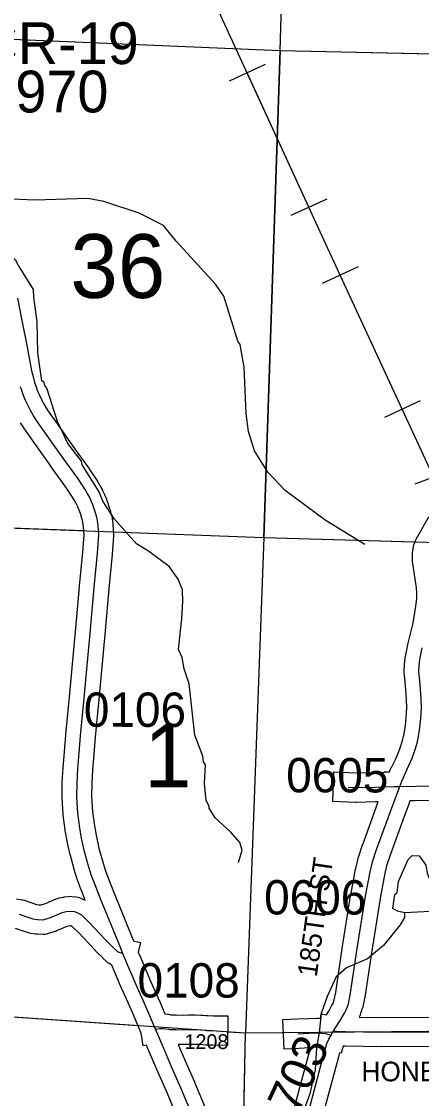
# Model space of a CAD drawing. Extents: x -132.8 to -73.3, y -60 to -26.
# Drawn here: x -122.216 to -121.401, y -45.505 to -43.311 of the extents above; entities that cross this region are included whole.
import ezdxf

# ---------------------------------------------------------------- set-up
doc = ezdxf.new("R2010")
doc.units = 0
for name, color, linetype in [('tdCoHydroRiver', 7, 'Continuous'), ('tdCoPipe', 7, 'Continuous'), ('tdCoSecRdNmbr', 7, 'Continuous'), ('tdCoSecRdTxt', 7, 'Continuous'), ('tdCoSecRteBand', 7, 'Continuous'), ('tdCoSecRteCL', 7, 'Continuous'), ('tdCoSectLine', 7, 'Continuous'), ('tdCoSectLinePart', 7, 'Continuous'), ('tdCoSectNmbr', 7, 'Continuous'), ('tdCoStrucSecCoName', 7, 'Continuous'), ('tdCoStrucSecFHWANum', 7, 'Continuous'), ('tdCoSurfAsphalt', 7, 'Continuous'), ('tdCoSurfBitum', 7, 'Continuous'), ('tdCoSurfGravel', 7, 'Continuous'), ('tdCoTwpBndry', 7, 'Continuous'), ('tdCoTwpBndryShd', 7, 'Continuous')]:
    doc.layers.add(name, color=color, linetype=linetype)

msp = doc.modelspace()

# ---------------------------------------------------------------- linework, layer by layer
at = {"layer": 'tdCoHydroRiver'}
for points in [[(-121.5159, -44.3765), (-121.5967, -44.3269), (-121.6787, -44.2663), (-121.714, -44.2291), (-121.7412, -44.1858), (-121.7528, -44.146), (-121.7581, -44.1096), (-121.7619, -44.0148), (-121.7701, -43.9689), (-121.7747, -43.9624), (-121.8037, -43.8701), (-121.8204, -43.846), (-121.9002, -43.7587), (-121.9261, -43.7264), (-121.9759, -43.7014), (-122.0479, -43.6774), (-122.0809, -43.6717), (-122.1883, -43.6751), (-122.2498, -43.6719)], [(-122.1839, -43.9229), (-122.1905, -43.8723), (-122.1916, -43.8565), (-122.2203, -43.81), (-122.2219, -43.8083), (-122.2264, -43.7987), (-122.2341, -43.7922), (-122.2501, -43.7413)], [(-122.1825, -43.9861), (-122.1839, -43.9229)], [(-121.7733, -45.0242), (-121.7663, -44.9991), (-121.7706, -44.9833), (-121.789, -44.9622), (-121.8213, -44.933), (-121.8334, -44.9137), (-121.8333, -44.909), (-121.8393, -44.8978), (-121.8431, -44.863), (-121.8405, -44.8252), (-121.8451, -44.8187), (-121.8463, -44.8077), (-121.8626, -44.7646), (-121.8739, -44.6602), (-121.8842, -44.6299), (-121.8883, -44.6062), (-121.8957, -44.5902), (-121.8893, -44.5273), (-121.8868, -44.4926), (-121.8877, -44.4689), (-121.8966, -44.4466), (-121.9148, -44.4209), (-121.9566, -44.3898), (-121.9815, -44.3749), (-122.0259, -44.3248), (-122.0501, -44.2878), (-122.0575, -44.2687), (-122.0924, -44.2141), (-122.0937, -44.2062), (-122.1212, -44.1708), (-122.1421, -44.126), (-122.1639, -44.0576), (-122.1685, -44.0527), (-122.1699, -44.0464), (-122.1745, -44.0431), (-122.1825, -43.9861)], [(-121.4351, -45.1264), (-121.4492, -45.1229), (-121.4586, -45.1179), (-121.4546, -45.0896), (-121.4498, -45.085), (-121.4476, -45.063), (-121.4275, -45.0178), (-121.4194, -45.0101), (-121.4052, -45.0105), (-121.3915, -45.0298), (-121.3887, -45.0457), (-121.3784, -45.0727), (-121.3758, -45.0918), (-121.3712, -45.0966), (-121.3687, -45.1235), (-121.4351, -45.1264)], [(-121.4351, -45.1264), (-121.4354, -45.1359), (-121.4437, -45.1514), (-121.4779, -45.1931), (-121.5103, -45.2206), (-121.5533, -45.2384), (-121.5744, -45.2568), (-121.5928, -45.2973), (-121.6048, -45.3317), (-121.609, -45.371), (-121.6145, -45.4008), (-121.6173, -45.4465), (-121.6281, -45.4951), (-121.6605, -45.5842)]]:
    msp.add_lwpolyline(points, dxfattribs=at)
at = {"layer": 'tdCoPipe'}
for p, q in [((-121.7192, -43.3986), (-121.7925, -43.4323)), ((-121.5935, -43.6725), (-121.6667, -43.7061)), ((-121.5298, -43.8105), (-121.603, -43.8444)), ((-121.4031, -44.0839), (-121.4762, -44.1178)), ((-121.3386, -44.2253), (-121.4143, -44.2532))]:
    msp.add_line(p, q, dxfattribs=at)
for points in [[(-119.9584, -47.7616), (-119.9471, -47.3844), (-120.3344, -46.3596), (-120.5772, -46.3668), (-120.6441, -46.2979), (-120.7015, -46.0564), (-120.837, -45.9047), (-120.8751, -45.6974), (-120.9717, -45.5088), (-121.2124, -44.6836), (-121.3801, -44.2294), (-121.5957, -43.7643), (-121.8285, -43.2571), (-122.1175, -42.7469), (-122.5487, -41.6141), (-122.6831, -41.5141), (-123.1262, -40.7823)], [(-121.6301, -43.6893), (-121.7558, -43.4155)], [(-121.4397, -44.1008), (-121.5664, -43.8275)]]:
    msp.add_lwpolyline(points, dxfattribs=at)
at = {"layer": 'tdCoSecRteBand'}
for points in [[(-122.2236, -43.8744), (-122.215, -43.9199), (-122.2044, -43.9738), (-122.2044, -43.9739), (-122.2044, -43.974), (-122.1951, -44.0228), (-122.1936, -44.0296), (-122.1916, -44.0367), (-122.189, -44.0462), (-122.1861, -44.055), (-122.1829, -44.0637), (-122.1793, -44.0723), (-122.1753, -44.0807), (-122.171, -44.0889), (-122.1664, -44.097), (-122.1615, -44.1047), (-122.1427, -44.1315), (-122.1063, -44.1829), (-122.0775, -44.223), (-122.0772, -44.2234), (-122.0769, -44.2238), (-122.0612, -44.2475), (-122.0607, -44.2482), (-122.0603, -44.2488), (-122.0558, -44.2564), (-122.0555, -44.257), (-122.0552, -44.2576), (-122.051, -44.2653), (-122.0507, -44.2659), (-122.0504, -44.2665), (-122.0467, -44.2745), (-122.0464, -44.2751), (-122.0461, -44.2757), (-122.0427, -44.2838), (-122.0424, -44.2844), (-122.0422, -44.2851), (-122.0392, -44.2933), (-122.039, -44.294), (-122.0388, -44.2946), (-122.0361, -44.303), (-122.0359, -44.3037), (-122.0357, -44.3043), (-122.0335, -44.3128), (-122.0333, -44.3135), (-122.0332, -44.3141), (-122.0313, -44.3227), (-122.0312, -44.3234), (-122.0311, -44.3241), (-122.0296, -44.3327), (-122.0294, -44.3344), (-122.0293, -44.3361), (-122.0283, -44.3553), (-122.0282, -44.3572), (-122.0283, -44.3591), (-122.031, -44.3963), (-122.0311, -44.3966), (-122.0311, -44.397), (-122.0377, -44.4669), (-122.0451, -44.5521), (-122.0451, -44.5522), (-122.0451, -44.5523), (-122.0493, -44.5966), (-122.058, -44.6918), (-122.058, -44.6918), (-122.058, -44.6919), (-122.0654, -44.769), (-122.0683, -44.8036), (-122.0683, -44.8037), (-122.0683, -44.8038), (-122.0712, -44.8352), (-122.0726, -44.8632), (-122.0731, -44.8896), (-122.071, -44.9209), (-122.0673, -44.9491), (-122.0638, -44.9687), (-122.058, -44.9948), (-122.0516, -45.0185), (-122.0444, -45.0414), (-122.0379, -45.0591), (-122.027, -45.0867), (-121.9906, -45.1758), (-121.9873, -45.1836), (-121.9731, -45.1869), (-121.9778, -45.2067), (-121.9734, -45.2172), (-121.9546, -45.261), (-121.9349, -45.3052), (-121.9348, -45.3054), (-121.9347, -45.3056), (-121.9269, -45.3239), (-121.9233, -45.3324), (-121.9177, -45.3331), (-121.9169, -45.3332), (-121.9161, -45.3333), (-121.9113, -45.3342), (-121.91, -45.3343), (-121.9068, -45.3345), (-121.9006, -45.3346), (-121.8875, -45.3348), (-121.8751, -45.3346), (-121.8749, -45.3346), (-121.8747, -45.3346), (-121.8636, -45.3346), (-121.8634, -45.3346), (-121.8633, -45.3346), (-121.85, -45.3348), (-121.8485, -45.3348), (-121.847, -45.335), (-121.8391, -45.3358), (-121.8362, -45.3361), (-121.8253, -45.3362), (-121.7953, -45.3366), (-121.796, -45.3966), (-121.826, -45.3962), (-121.8382, -45.3961), (-121.8395, -45.3961), (-121.8408, -45.396), (-121.8452, -45.3955), (-121.8453, -45.3955), (-121.8455, -45.3955), (-121.8521, -45.3948), (-121.8638, -45.3946), (-121.8746, -45.3946), (-121.8871, -45.3948), (-121.8875, -45.3948), (-121.8878, -45.3948), (-121.8966, -45.3947), (-121.8823, -45.428), (-121.8634, -45.4707), (-121.8632, -45.4711), (-121.8631, -45.4714), (-121.8402, -45.5265)], [(-122.2262, -45.098), (-122.2151, -45.1), (-122.2128, -45.1004), (-122.2106, -45.1011), (-122.195, -45.1065), (-122.1855, -45.1096), (-122.1803, -45.1104), (-122.1754, -45.1105), (-122.1668, -45.1079), (-122.1448, -45.0983), (-122.142, -45.0971), (-122.139, -45.0964), (-122.1309, -45.0947), (-122.1296, -45.0944), (-122.1283, -45.0943), (-122.1201, -45.0933), (-122.1167, -45.0929), (-122.1132, -45.0933), (-122.1043, -45.0942), (-122.1003, -45.0947), (-122.0965, -45.0962), (-122.0891, -45.0992), (-122.0874, -45.0999), (-122.086, -45.1006), (-122.0938, -45.0808), (-122.0939, -45.0805), (-122.094, -45.0802), (-122.1009, -45.0614), (-122.1012, -45.0608), (-122.1014, -45.0601), (-122.109, -45.036), (-122.1092, -45.0353), (-122.1094, -45.0347), (-122.1161, -45.0098), (-122.1162, -45.0092), (-122.1164, -45.0086), (-122.1225, -44.9812), (-122.1227, -44.9805), (-122.1228, -44.9798), (-122.1265, -44.9589), (-122.1266, -44.9582), (-122.1267, -44.9576), (-122.1307, -44.9278), (-122.1308, -44.9268), (-122.1308, -44.9258), (-122.1331, -44.8923), (-122.1331, -44.891), (-122.1331, -44.8898), (-122.1326, -44.8617), (-122.1326, -44.8612), (-122.1326, -44.8607), (-122.1311, -44.8316), (-122.1311, -44.8309), (-122.131, -44.8303), (-122.1281, -44.7984), (-122.1251, -44.7637), (-122.1251, -44.7635), (-122.1251, -44.7634), (-122.1177, -44.6863), (-122.1091, -44.5912), (-122.1091, -44.5911), (-122.1091, -44.591), (-122.1049, -44.5468), (-122.0975, -44.4616), (-122.0975, -44.4614), (-122.0975, -44.4613), (-122.0909, -44.3916), (-122.0883, -44.3566), (-122.0891, -44.3409), (-122.0902, -44.3346), (-122.0917, -44.3274), (-122.0936, -44.3203), (-122.0958, -44.3133), (-122.0983, -44.3064), (-122.1012, -44.2996), (-122.1043, -44.2929), (-122.1078, -44.2864), (-122.1115, -44.2801), (-122.1266, -44.2576), (-122.1551, -44.2178), (-122.1552, -44.2177), (-122.1552, -44.2176), (-122.1917, -44.1661), (-122.1918, -44.166), (-122.1918, -44.166), (-122.211, -44.1386), (-122.2115, -44.138), (-122.2118, -44.1374), (-122.2175, -44.1285)], [(-121.6619, -45.533), (-121.6311, -45.417), (-121.6311, -45.4168), (-121.631, -45.4166), (-121.6268, -45.4018), (-121.6287, -45.4018), (-121.6507, -45.4028), (-121.6807, -45.4041), (-121.6833, -45.3442), (-121.6533, -45.3428), (-121.6312, -45.3419), (-121.6309, -45.3418), (-121.6306, -45.3418), (-121.6124, -45.3413), (-121.611, -45.3413), (-121.6095, -45.3414), (-121.6066, -45.3416), (-121.6053, -45.3327), (-121.5943, -45.3343), (-121.5896, -45.3268), (-121.5836, -45.3164), (-121.5808, -45.311), (-121.5786, -45.3041), (-121.5752, -45.2888), (-121.5628, -45.2038), (-121.5627, -45.2036), (-121.5627, -45.2034), (-121.5442, -45.0878), (-121.5441, -45.0873), (-121.5441, -45.0869), (-121.5347, -45.0374), (-121.5346, -45.0368), (-121.5344, -45.0362), (-121.5298, -45.0159), (-121.5294, -45.0146), (-121.529, -45.0132), (-121.5206, -44.9881), (-121.5205, -44.9877), (-121.5203, -44.9873), (-121.4922, -44.9099), (-121.4922, -44.9097), (-121.4921, -44.9096), (-121.4887, -44.9004), (-121.4936, -44.9006), (-121.4938, -44.9006), (-121.494, -44.9006), (-121.5327, -44.9016), (-121.5337, -44.9017), (-121.5348, -44.9016), (-121.5515, -44.9009), (-121.5815, -44.8996), (-121.5789, -44.8396), (-121.5489, -44.8409), (-121.5332, -44.8416), (-121.4957, -44.8407), (-121.4754, -44.8399), (-121.4754, -44.8395), (-121.4658, -44.8393), (-121.4625, -44.8304), (-121.4613, -44.8308), (-121.4544, -44.8158), (-121.4475, -44.8002), (-121.4432, -44.7883), (-121.4386, -44.7732), (-121.436, -44.7618), (-121.4334, -44.7452), (-121.4316, -44.7285), (-121.4307, -44.7089), (-121.4314, -44.6921), (-121.4333, -44.6636), (-121.4355, -44.6359), (-121.4356, -44.6344), (-121.4356, -44.6328), (-121.4353, -44.6227), (-121.4353, -44.6216), (-121.4352, -44.6206), (-121.434, -44.6078), (-121.4338, -44.606), (-121.4334, -44.6043), (-121.4282, -44.5804), (-121.4282, -44.5801), (-121.4281, -44.5798), (-121.4184, -44.5391), (-121.4142, -44.5157), (-121.4114, -44.4975), (-121.4102, -44.4859), (-121.41, -44.4753), (-121.4108, -44.4645), (-121.4148, -44.4373), (-121.4182, -44.4152), (-121.4185, -44.4132), (-121.4186, -44.4112), (-121.4188, -44.3986), (-121.4189, -44.3961), (-121.4185, -44.3935), (-121.4165, -44.3807), (-121.416, -44.3772), (-121.4146, -44.3739), (-121.4102, -44.363), (-121.4094, -44.361), (-121.4083, -44.3592), (-121.3853, -44.3202)], [(-121.2783, -44.8962), (-121.4144, -44.8985), (-121.424, -44.8986), (-121.4273, -44.9076), (-121.4359, -44.9305), (-121.4638, -45.0074), (-121.4716, -45.0309), (-121.4758, -45.0491), (-121.485, -45.0977), (-121.5034, -45.2127), (-121.516, -45.2986), (-121.5161, -45.2997), (-121.5164, -45.3007), (-121.5203, -45.3185), (-121.5206, -45.3199), (-121.5211, -45.3213), (-121.5245, -45.3319), (-121.5253, -45.3342), (-121.5264, -45.3363), (-121.5277, -45.3389), (-121.4816, -45.3398), (-121.3625, -45.3391)], [(-121.8956, -45.5496), (-121.9184, -45.4947), (-121.9372, -45.4521), (-121.9373, -45.452), (-121.9373, -45.4518), (-121.9549, -45.4111), (-121.9549, -45.4111), (-121.9549, -45.4111), (-121.9612, -45.3963), (-121.968, -45.3973), (-121.9718, -45.3715), (-121.9898, -45.3294), (-122.0095, -45.2852), (-122.0095, -45.285), (-122.0096, -45.2849), (-122.0253, -45.2484), (-122.0254, -45.2484), (-122.0317, -45.2332), (-122.0332, -45.2323), (-122.0379, -45.2293), (-122.0404, -45.2277), (-122.0426, -45.2256), (-122.049, -45.2194), (-122.0492, -45.2193), (-122.0493, -45.2192), (-122.0656, -45.2031), (-122.066, -45.2027), (-122.0665, -45.2022), (-122.0997, -45.1665), (-122.1116, -45.155), (-122.1132, -45.1542), (-122.115, -45.1534), (-122.1164, -45.1533), (-122.1197, -45.1537), (-122.1236, -45.1545), (-122.1445, -45.1636), (-122.1461, -45.1644), (-122.1479, -45.1649), (-122.1627, -45.1693), (-122.1672, -45.1707), (-122.1719, -45.1706), (-122.1835, -45.1703), (-122.1855, -45.1703), (-122.1874, -45.17), (-122.1971, -45.1685), (-122.1995, -45.1681), (-122.2018, -45.1674), (-122.2139, -45.1634), (-122.2141, -45.1634), (-122.2143, -45.1633), (-122.2279, -45.1586)], [(-121.3621, -45.3991), (-121.4817, -45.3998), (-121.4821, -45.3998), (-121.4825, -45.3998), (-121.5557, -45.3984), (-121.556, -45.3984), (-121.5563, -45.3983), (-121.5599, -45.3982), (-121.564, -45.4127), (-121.5673, -45.4118), (-121.5732, -45.4326), (-121.604, -45.5485)]]:
    msp.add_lwpolyline(points, dxfattribs=at)
at = {"layer": 'tdCoSecRteCL'}
for points in [[(-122.0092, -45.2092), (-122.0183, -45.1872), (-122.0548, -45.0979), (-122.0659, -45.0698), (-122.0728, -45.0511), (-122.0804, -45.0269), (-122.0871, -45.002), (-122.0933, -44.9746), (-122.097, -44.9537), (-122.1009, -44.9238), (-122.1031, -44.8903), (-122.1026, -44.8622), (-122.1012, -44.8331), (-122.0982, -44.801), (-122.0952, -44.7662), (-122.0878, -44.6891), (-122.0792, -44.5939), (-122.075, -44.5495), (-122.0676, -44.4642), (-122.061, -44.3941), (-122.0582, -44.3569), (-122.0592, -44.3376), (-122.0607, -44.329), (-122.0625, -44.3204), (-122.0648, -44.312), (-122.0674, -44.3036), (-122.0704, -44.2954), (-122.0738, -44.2873), (-122.0775, -44.2794), (-122.0816, -44.2717), (-122.0861, -44.2642), (-122.1019, -44.2405), (-122.1307, -44.2003), (-122.1672, -44.1487), (-122.1865, -44.1214), (-122.1921, -44.1125), (-122.1974, -44.1033), (-122.2022, -44.094), (-122.2067, -44.0844), (-122.2108, -44.0747), (-122.2144, -44.0648), (-122.2177, -44.0548)], [(-121.4449, -44.869), (-121.4408, -44.8582), (-121.427, -44.8281), (-121.4196, -44.8114), (-121.4147, -44.7978), (-121.4095, -44.7808), (-121.4066, -44.7675), (-121.4036, -44.7492), (-121.4016, -44.7307), (-121.4007, -44.709), (-121.4014, -44.6905), (-121.4034, -44.6614), (-121.4056, -44.6336), (-121.4053, -44.6235), (-121.4041, -44.6106), (-121.3989, -44.5867)], [(-121.58, -45.3667), (-121.5735, -45.3576), (-121.5639, -45.3423), (-121.5572, -45.3307), (-121.5531, -45.3226), (-121.5496, -45.312), (-121.5457, -45.2942), (-121.5331, -45.2082), (-121.5146, -45.0925), (-121.5052, -45.0429), (-121.5005, -45.0227), (-121.4921, -44.9976), (-121.464, -44.9201), (-121.4449, -44.869)], [(-121.5502, -44.8709), (-121.5334, -44.8716), (-121.4947, -44.8707), (-121.4565, -44.8692), (-121.4449, -44.869)], [(-121.4449, -44.869), (-121.2787, -44.8662), (-121.1248, -44.865), (-121.0661, -44.864)], [(-122.2204, -45.1295), (-122.2046, -45.1349), (-122.1925, -45.1389), (-122.1829, -45.1403), (-122.1713, -45.1406), (-122.1565, -45.1361), (-122.1328, -45.1258), (-122.1247, -45.1241), (-122.1165, -45.1231), (-122.1077, -45.1241), (-122.1003, -45.127), (-122.0936, -45.1307), (-122.0783, -45.1455), (-122.0445, -45.1818), (-122.0283, -45.1978), (-122.0218, -45.204), (-122.0172, -45.2069), (-122.0127, -45.2084), (-122.0092, -45.2092)], [(-121.9427, -45.3633), (-121.9623, -45.3174), (-121.982, -45.273), (-122.001, -45.2289), (-122.0092, -45.2092)], [(-121.9427, -45.3633), (-121.9339, -45.362), (-121.9273, -45.3621), (-121.9213, -45.3629), (-121.9154, -45.3639), (-121.9125, -45.3642), (-121.9081, -45.3645), (-121.9011, -45.3646), (-121.8875, -45.3648), (-121.8747, -45.3646), (-121.8636, -45.3646), (-121.8503, -45.3648), (-121.8422, -45.3657), (-121.8378, -45.3661), (-121.8257, -45.3662)], [(-121.7447, -45.8273), (-121.7611, -45.7882), (-121.7761, -45.7522), (-121.8097, -45.6738), (-121.8447, -45.5921), (-121.8679, -45.5381), (-121.8908, -45.4829), (-121.9098, -45.44), (-121.9273, -45.3993), (-121.9427, -45.3633)], [(-121.5848, -45.3757), (-121.5812, -45.3685), (-121.58, -45.3667)], [(-121.58, -45.3667), (-121.5738, -45.3676), (-121.5551, -45.3684), (-121.4819, -45.3698), (-121.3623, -45.3691)], [(-121.7447, -45.8273), (-121.7406, -45.8247), (-121.7193, -45.8099), (-121.7129, -45.8045), (-121.7074, -45.7985), (-121.7037, -45.7934), (-121.6998, -45.7864), (-121.6953, -45.7734), (-121.6658, -45.6614), (-121.633, -45.5408), (-121.6021, -45.4247), (-121.5933, -45.3931), (-121.5891, -45.3842), (-121.5848, -45.3757)], [(-121.652, -45.3728), (-121.6298, -45.3718), (-121.6116, -45.3713), (-121.597, -45.3723), (-121.5848, -45.3757)]]:
    msp.add_lwpolyline(points, dxfattribs=at)
at = {"layer": 'tdCoSectLine'}
for points in [[(-121.6884, -43.3703), (-121.6589, -42.3688)], [(-122.6865, -43.3276), (-121.6884, -43.3703)], [(-121.6884, -43.3703), (-121.7221, -44.3617)], [(-121.6884, -43.3703), (-120.7492, -43.3906)], [(-122.7152, -44.3247), (-121.7221, -44.3617)], [(-121.7221, -44.3617), (-121.7592, -45.3712)], [(-121.7221, -44.3617), (-120.7507, -44.3901)], [(-122.7257, -45.3043), (-121.7592, -45.3712)], [(-121.7592, -45.3712), (-120.7927, -45.3624)], [(-121.7789, -46.3599), (-121.7592, -45.3712)]]:
    msp.add_lwpolyline(points, dxfattribs=at)
at = {"layer": 'tdCoSectLinePart'}
for points in [[(-121.6884, -43.3703), (-121.6707, -42.7686)], [(-122.331, -43.3428), (-121.6884, -43.3703)], [(-121.6884, -43.3703), (-121.7221, -44.3617)], [(-121.6884, -43.3703), (-121.0063, -43.385)], [(-122.7152, -44.3247), (-122.0894, -44.348)], [(-122.0291, -44.3502), (-121.7221, -44.3617)], [(-121.7221, -44.3617), (-121.7592, -45.3712)], [(-121.7221, -44.3617), (-121.4136, -44.3707)], [(-122.7257, -45.3043), (-121.9789, -45.356)], [(-121.7961, -45.3687), (-121.7592, -45.3712)], [(-121.7658, -45.7018), (-121.7592, -45.3712)], [(-121.7592, -45.3712), (-121.6825, -45.3705)]]:
    msp.add_lwpolyline(points, dxfattribs=at)
at = {"layer": 'tdCoSurfAsphalt'}
msp.add_lwpolyline([(-121.8679, -45.5381), (-121.8908, -45.4829), (-121.9098, -45.44), (-121.9273, -45.3993), (-121.9427, -45.3633), (-121.9623, -45.3174), (-121.982, -45.273), (-122.001, -45.2289), (-122.0092, -45.2092), (-122.0183, -45.1872), (-122.0548, -45.0979), (-122.0659, -45.0698), (-122.0728, -45.0511), (-122.0804, -45.0269), (-122.0871, -45.002), (-122.0933, -44.9746), (-122.097, -44.9537), (-122.1009, -44.9238), (-122.1031, -44.8903), (-122.1026, -44.8622), (-122.1012, -44.8331), (-122.0982, -44.801), (-122.0952, -44.7662), (-122.0878, -44.6891), (-122.0792, -44.5939), (-122.075, -44.5495), (-122.0676, -44.4642), (-122.061, -44.3941), (-122.0582, -44.3569), (-122.0592, -44.3376), (-122.0607, -44.329), (-122.0625, -44.3204), (-122.0648, -44.312), (-122.0674, -44.3036), (-122.0704, -44.2954), (-122.0738, -44.2873), (-122.0775, -44.2794), (-122.0816, -44.2717), (-122.0861, -44.2642), (-122.1019, -44.2405), (-122.1307, -44.2003), (-122.1672, -44.1487), (-122.1865, -44.1214), (-122.1921, -44.1125), (-122.1974, -44.1033), (-122.2022, -44.094), (-122.2067, -44.0844), (-122.2108, -44.0747), (-122.2144, -44.0648), (-122.2177, -44.0548)], dxfattribs=at)
at = {"layer": 'tdCoSurfBitum'}
msp.add_lwpolyline([(-121.633, -45.5408), (-121.6021, -45.4247), (-121.5933, -45.3931), (-121.5891, -45.3842), (-121.5848, -45.3757), (-121.5812, -45.3685), (-121.58, -45.3667), (-121.5735, -45.3576), (-121.5639, -45.3423), (-121.5572, -45.3307), (-121.5531, -45.3226), (-121.5496, -45.312), (-121.5457, -45.2942), (-121.5331, -45.2082), (-121.5146, -45.0925), (-121.5052, -45.0429), (-121.5005, -45.0227), (-121.4921, -44.9976), (-121.464, -44.9201), (-121.4449, -44.869), (-121.4408, -44.8582), (-121.427, -44.8281), (-121.4196, -44.8114), (-121.4147, -44.7978), (-121.4095, -44.7808), (-121.4066, -44.7675), (-121.4036, -44.7492), (-121.4016, -44.7307), (-121.4007, -44.709), (-121.4014, -44.6905), (-121.4034, -44.6614), (-121.4056, -44.6336), (-121.4053, -44.6235), (-121.4041, -44.6106), (-121.3989, -44.5867)], dxfattribs=at)
at = {"layer": 'tdCoSurfGravel'}
for points in [[(-121.5502, -44.8709), (-121.5334, -44.8716), (-121.4947, -44.8707), (-121.4565, -44.8692), (-121.4449, -44.869)], [(-121.4449, -44.869), (-121.2787, -44.8662), (-121.1248, -44.865), (-121.0661, -44.864)], [(-122.2204, -45.1295), (-122.2046, -45.1349), (-122.1925, -45.1389), (-122.1829, -45.1403), (-122.1713, -45.1406), (-122.1565, -45.1361), (-122.1328, -45.1258), (-122.1247, -45.1241), (-122.1165, -45.1231), (-122.1077, -45.1241), (-122.1003, -45.127), (-122.0936, -45.1307), (-122.0783, -45.1455), (-122.0445, -45.1818), (-122.0283, -45.1978), (-122.0218, -45.204), (-122.0172, -45.2069), (-122.0127, -45.2084), (-122.0092, -45.2092)], [(-121.9427, -45.3633), (-121.9339, -45.362), (-121.9273, -45.3621), (-121.9213, -45.3629), (-121.9154, -45.3639), (-121.9125, -45.3642), (-121.9081, -45.3645), (-121.9011, -45.3646), (-121.8875, -45.3648), (-121.8747, -45.3646), (-121.8636, -45.3646), (-121.8503, -45.3648), (-121.8422, -45.3657), (-121.8378, -45.3661), (-121.8257, -45.3662)], [(-121.58, -45.3667), (-121.5738, -45.3676), (-121.5551, -45.3684), (-121.4819, -45.3698), (-121.3623, -45.3691), (-121.1896, -45.3674), (-121.0101, -45.3642), (-120.9373, -45.3622), (-120.9295, -45.3617)], [(-121.652, -45.3728), (-121.6298, -45.3718), (-121.6116, -45.3713), (-121.597, -45.3723), (-121.5848, -45.3757)]]:
    msp.add_lwpolyline(points, dxfattribs=at)
at = {"layer": 'tdCoTwpBndry'}
for points in [[(-121.7221, -44.3617), (-121.6884, -43.3703), (-121.6707, -42.7687)], [(-122.7605, -44.3232), (-122.7152, -44.3247), (-122.0891, -44.348)], [(-122.0281, -44.3503), (-121.7221, -44.3617), (-121.4154, -44.3707)]]:
    msp.add_lwpolyline(points, dxfattribs=at)
at = {"layer": 'tdCoTwpBndryShd'}
for points in [[(-121.7221, -44.3617), (-121.6884, -43.3703), (-121.6589, -42.3688), (-121.6344, -41.3624), (-121.6038, -40.3885), (-121.5951, -39.3869), (-121.5447, -38.3793), (-121.5152, -37.3893), (-121.4844, -36.3817), (-121.4457, -35.3996), (-121.4178, -34.4045), (-121.3879, -33.4095), (-121.3677, -32.38)], [(-127.2202, -44.1954), (-126.6973, -44.2087), (-125.6932, -44.234), (-124.6944, -44.2641), (-123.6992, -44.2925), (-122.7152, -44.3247), (-121.7221, -44.3617), (-120.7507, -44.3901), (-119.7594, -44.4268), (-118.768, -44.449), (-117.7739, -44.4798), (-116.7726, -44.5066), (-115.7834, -44.5349), (-114.8143, -44.5585)]]:
    msp.add_lwpolyline(points, dxfattribs=at)

# ---------------------------------------------------------------- texts
at = {"layer": 'tdCoSecRdNmbr'}
for s, height, rotation, p in [('0106', 0.07, 359.9085, (-122.0887, -44.7476)), ('0605', 0.07, 359.9091, (-121.6763, -44.8811)), ('0606', 0.07, 359.9092, (-121.7213, -45.1299)), ('0108', 0.07, 359.9085, (-121.9793, -45.299)), ('1208', 0.03, 359.9094, (-121.8835, -45.4039)), ('0703', 0.07, 64.909, (-121.6754, -45.5876))]:
    msp.add_text(s, height=height, rotation=rotation, dxfattribs=at).set_placement(p)
at = {"layer": 'tdCoSecRdTxt'}
for s, rotation, p in [('185TH ST', 82.049, (-121.6141, -45.2586)), ('HONEYSUCKLE RD', 0.1886, (-121.5228, -45.47))]:
    msp.add_text(s, height=0.04, rotation=rotation, dxfattribs=at).set_placement(p)
at = {"layer": 'tdCoSectNmbr'}
for s, rotation, p in [('36', 359.9086, (-122.1162, -43.8739)), ('1', 359.9087, (-121.9657, -44.8707))]:
    msp.add_text(s, height=0.13, rotation=rotation, dxfattribs=at).set_placement(p)
at = {"layer": 'tdCoStrucSecCoName'}
msp.add_text('CR-19', height=0.085, dxfattribs=at).set_placement((-122.3054, -43.3976))
at = {"layer": 'tdCoStrucSecFHWANum'}
msp.add_text('43970', height=0.085, dxfattribs=at).set_placement((-122.3547, -43.4961))

doc.saveas('drawing.dxf')
